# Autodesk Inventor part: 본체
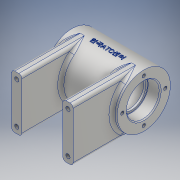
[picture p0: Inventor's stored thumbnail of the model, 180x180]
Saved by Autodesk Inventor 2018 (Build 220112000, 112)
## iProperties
Created: 2020-07
Part Number: 본체
Material: Aluminum 6061
Document SubType Name: Modeling
Designer: Administrator
Density: 2.7 g/cm^3
Appearance: Aluminum - Flat
Mass: 305.265 g
Surface Area: 357.564 cm^2
Volume: 113.061 cm^3
Author: Administrator
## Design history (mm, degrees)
sketch "Sketch1"
  geometry: L1 (0, 26)-(-35, 26); L2 (0, 26)-(35, 26); L3 (-35, 26)-(-35, 16); L4 (-35, 16)-(-23.3, 16); L5 (-23, 15.7)-(-23, 14); L6 (-23, 14)-(-21, 14); L7 (-21, 14)-(-21, 18); L8 (-18, 21)-(18, 21); L9 (21, 18)-(21, 14); L10 (21, 14)-(23, 14); L11 (23, 14)-(23, 15.7); L12 (23.3, 16)-(35, 16); L13 (35, 16)-(35, 26); L14 (-35, 0)-(35, 0); A1 r 0.3 centre (-23.3, 15.7) between (-23, 15.7) and (-23.3, 16); A2 r 0.3 centre (23.3, 15.7) between (23.3, 16) and (23, 15.7); A3 r 3 centre (18, 18) between (21, 18) and (18, 21); A4 r 3 centre (-18, 18) between (-18, 21) and (-21, 18); 5 further points
  constraints: 28 end point, 9 perpendicular, 8 point on circle, 8 point on line, 8 tangent, 4 centre point, 2 equal radius, 2 horizontal, 2 vertical
  dimensions: "d1" = 35 distance of L1.start L1.end; "d2" = 35 distance of L1.start L2.end; "d3" = 10 distance of L1.end L3.end; "d4" = 12 distance of L3.end point (-23, 16); "d5" = 2 distance of point (-23, 16) L5.end; "d6" = 2 distance of L5.end L6.end; "d7" = 7 distance of L6.end point (-21, 21); "d8" = 42 distance of point (-21, 21) point (21, 21); "d9" = 7 distance of point (21, 21) L9.end; "d10" = 2 distance of L9.end L10.end; "d11" = 2 distance of L10.end point (23, 16); "d12" = 12 distance of point (23, 16) L12.end; "d13" = 0.3 radius of A1; "d14" = 3 radius of A3
revolve "Revolution1" sketch "Sketch1" stored, may be unused: angle "d15" = 90 deg
sketch "Sketch2"
  geometry: L1 (0, 23.558)-(0, 29); L2 (0, 29)-(5, 29); L3 (0, 23.558)-(5, 23.558); L4 (5, 23.558)-(5, 29); 1 further point
  constraints: 8 end point, 2 horizontal, 1 perpendicular, 1 vertical
  dimensions: "d18" = 5.442 distance of L1.start L1.end; "d19" = 5 distance of L1.end L2.end
revolve "Revolution2" sketch "Sketch2" stored, may be unused: angle "d20" = 90 deg
sketch "Sketch3"
  geometry: 2 further points
  constraints: 1 coincident
hole "Hole1" sketch "Sketch3" at (0, 0) diameter "d21" = 5.188; stored, may be unused: countersink angle "d25" = 90 deg, drill point angle "d27" = 118 deg; dims "d22" = 16, "d23" = 4, "d24" = 2, "d26" = 16
fillet "Fillet1" dims "d28" = 2
sketch "Sketch4"
  geometry: L1 (0, 0)-(-56.537, -20.578); L2 (0, 0)-(-32.45, 0); L3 (-21.871, -7.961)-(-19.819, -13.599); L4 (-19.819, -13.599)-(-25.199, -15.557); L5 (-25.199, -15.557)-(-27.251, -9.919); C1 r 26 at (0, 0) reference
  constraints: 10 end point, 2 perpendicular, 2 point on line, 1 horizontal, 1 parallel
  dimensions: "d31" = 20 deg angle of L2 L1; "d32" = 29 distance from line of L1.start L5; "d33" = 12 diameter of L4 L1; "d34" = 5.72494 distance between parallel lines of L3 L5; "d35" = 17.09868 distance from line of L2.end L4; "d36" = 20.57767 distance from line of L1.end L2
revolve "Revolution3" sketch "Sketch4" stored, may be unused: angle "d37" = 90 deg
sketch "Sketch5"
  geometry: 2 further points
  constraints: 1 coincident
hole "Hole2" sketch "Sketch5" at (0, 0) diameter "d38" = 5.188; stored, may be unused: countersink angle "d42" = 90 deg, drill point angle "d44" = 118 deg; dims "d39" = 16, "d40" = 4, "d41" = 2, "d43" = 16
fillet "Fillet2" dims "d45" = 2
workplane "Work Plane1"
sketch "Sketch6"
  geometry: L1 (0, 26)-(-64, 26); L2 (0, -26)-(-64, -26); L3 (-64, 26)-(-64, -26); A1 r 26 centre (0, 0) between (0, 26) and (0, -26) reference; 1 further point
  constraints: 6 end point, 2 horizontal, 2 point on circle, 2 tangent
  dimensions: "d49" = 64 distance of L1.start L1.end; "d50" = 64 distance of L2.start L2.end
extrude "Extrusion1" join sketch "Sketch6" stored distance "d51" = 10; taper "d52" = 0 deg
mirror "Mirror1"
fillet "Fillet3" dims "d53" = 3
sketch "Sketch7"
  geometry: 5 further points
hole "Hole3" sketch "Sketch7" at (0, 21), (-21, 0), (0, -21), (21, 0) diameter "d55" = 3.242; stored, may be unused: countersink angle "d59" = 90 deg, drill point angle "d61" = 118 deg; dims "d56" = 8, "d57" = 4, "d58" = 2, "d60" = 10
mirror "Mirror2"
sketch "Sketch8"
  geometry: L1 (-3, 49)-(-3, 3) reference; L2 (47, 49)-(47, 3) reference; 5 further points
hole "Hole4" sketch "Sketch8" at (2, 46), (2, 6), (52, 46), (52, 6) diameter "d68" = 4.134; stored, may be unused: countersink angle "d72" = 90 deg, drill point angle "d74" = 118 deg; dims "d69" = 8, "d70" = 4, "d71" = 2, "d73" = 10
workplane "Work Plane2"
sketch "Sketch9"
  geometry: L1 (35, -26)-(35, 26) reference; L2 (-35, -26)-(-35, 26) reference; 2 further points
  constraints: 1 other
  dimensions: "d76" = 35 distance from line of point (0, 0) L2 (derived); "d77" = 26 vertical distance of point (0, 0) L2.end (derived)
emboss "Emboss1" sketch "Sketch9" dims "d1" = 35, "d2" = 35, "d3" = 10, "d4" = 12, "d5" = 2, "d6" = 2, "d7" = 7, "d8" = 42, "d9" = 7, "d10" = 2, "d11" = 2, "d12" = 12, "d13" = 0.3, "d14" = 3, "d78" = 0.5, "d79" = 0
chamfer "Chamfer1" distance "d80" = 1; stored, may be unused: second distance "d81" = 2, angle "d82" = 45 deg
chamfer "Chamfer2" distance "d83" = 1; stored, may be unused: second distance "d84" = 2, angle "d85" = 45 deg
body "Solid1"
other parameters: "d46" = 25, "d75" = 26
